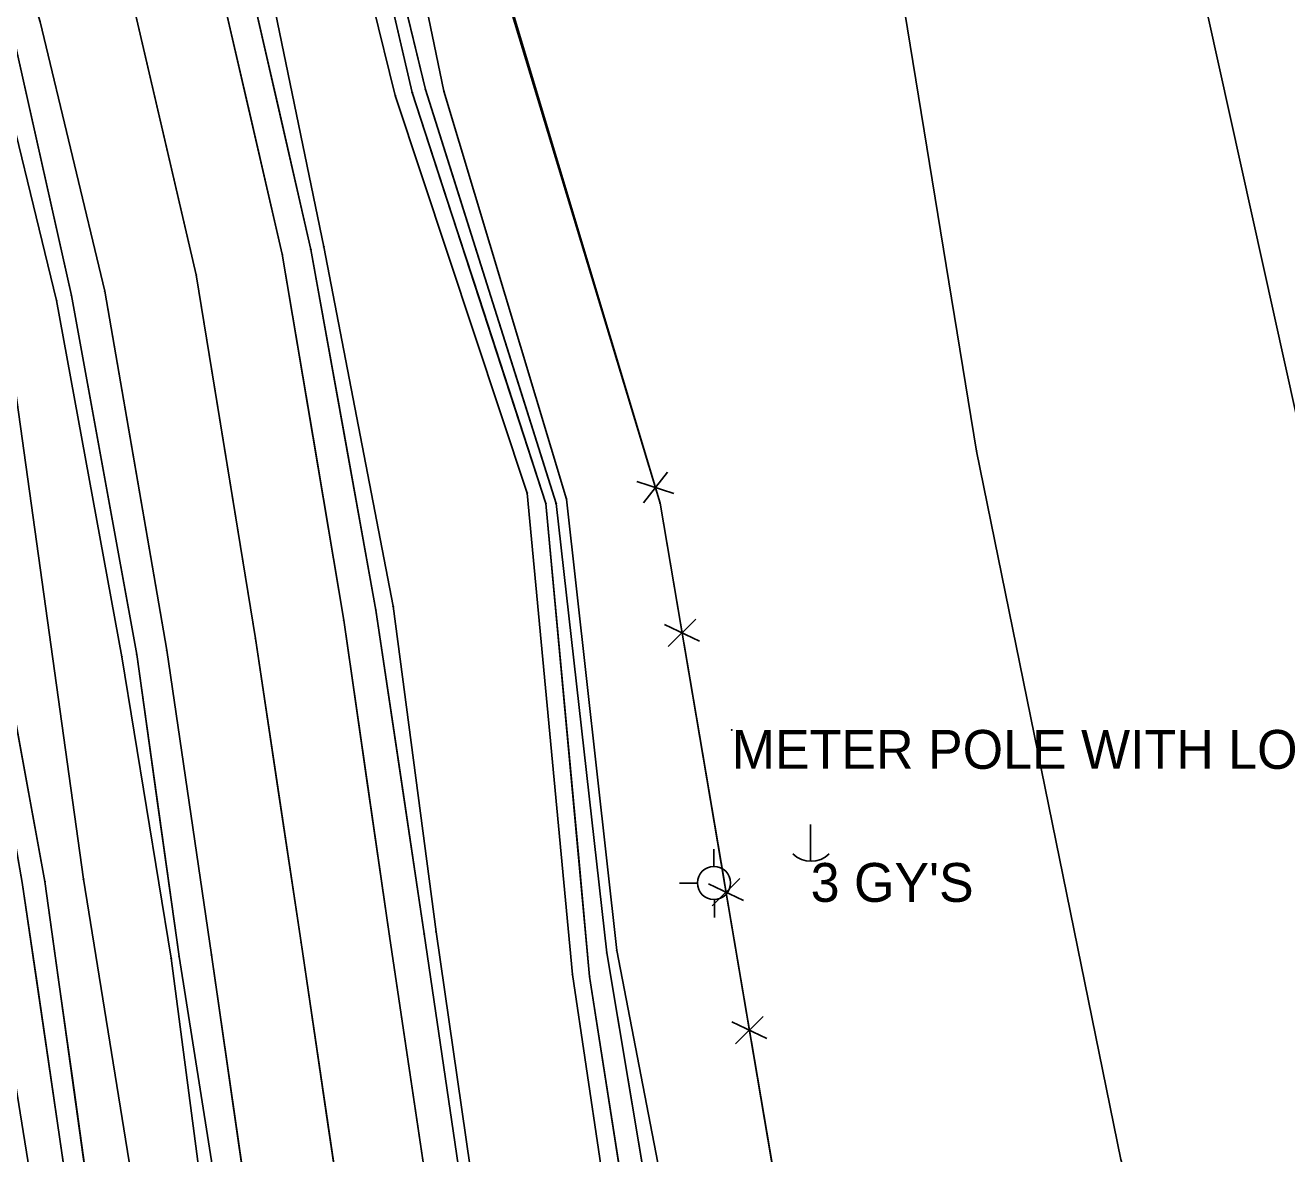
# Model space of a CAD drawing. Extents: x -99999 to 591807, y -99999 to 347168.
# Drawn here: x 588596 to 588758.3, y 345658.1 to 345803.3 of the extents above; entities that cross this region are included whole.
import ezdxf

# ---------------------------------------------------------------- set-up
doc = ezdxf.new("R2010")
doc.units = 0
for name, color, linetype in [('S_BREAKLINE', 7, 'Continuous'), ('S_DITCHLINE', 7, 'Continuous'), ('S_EDGE_PAVEMENT', 7, 'Continuous'), ('S_FENCE', 7, 'Continuous'), ('S_GRD_PT_SYM', 7, 'Continuous'), ('S_MISC_STRUCTURES_ANNOT', 7, 'Continuous'), ('S_MSC_PT_SYM', 7, 'Continuous'), ('S_PAVEMENT_CROWN', 7, 'Continuous'), ('S_RDW_PT_SYM', 7, 'Continuous'), ('S_SHOULDER', 7, 'Continuous'), ('S_UTILITY_POLE', 7, 'Continuous'), ('S_UTILITY_POLE_ANNOT', 7, 'Continuous')]:
    doc.layers.add(name, color=color, linetype=linetype)

msp = doc.modelspace()

# ---------------------------------------------------------------- linework, layer by layer
at = {"layer": 'S_BREAKLINE'}
for points in [[(588528.51, 345946.61), (588543.27, 345921.4), (588554.67, 345900.36), (588570.47, 345864.64), (588581.65, 345836.71), (588591.74, 345801.57), (588600, 345767.86), (588608.39, 345722.01), (588614.74, 345683.21), (588620.99, 345635.46), (588626.69, 345599.06), (588633.41, 345553.71), (588638.96, 345515.87), (588645.67, 345465.33), (588651.24, 345429.08)], [(588709.23, 345917.41), (588738.28, 345849.11), (588759.52, 345753.19), (588776.45, 345663.8), (588799.17, 345587.06), (588826.92, 345501.14), (588855.64, 345416.24), (588845.53, 345290.12), (588847.65, 345252.05)], [(588624.24, 345901.93), (588618.85, 345902.22), (588605.5, 345880.61), (588615.62, 345846.94), (588626.77, 345811.58), (588634.39, 345774.77), (588643.3, 345728.51), (588648.82, 345686.6), (588655.41, 345641.18), (588661.15, 345603.84), (588667.75, 345558.22), (588673.72, 345520.6), (588680.03, 345471.84), (588686.17, 345431.09), (588691.15, 345391.28), (588697.45, 345351.38), (588702.87, 345317.84), (588708.54, 345276.89), (588714.45, 345238.55), (588718.86, 345198.93), (588725.64, 345160.39), (588730.67, 345119.29), (588731.09, 345112.27)], [(588685.76, 345901.75), (588702.37, 345846.43), (588718.38, 345748.49), (588736.94, 345657.3), (588761.62, 345575.96), (588787.42, 345488.29), (588814.88, 345403.52), (588808.38, 345294.83), (588809.34, 345255.32)], [(588617.74, 345892.11), (588627.02, 345863.98), (588634.95, 345829.29), (588643.57, 345794.26), (588660.55, 345743.08), (588666.37, 345681.13), (588673.4, 345633.78), (588679.09, 345577.18), (588687.3, 345524.37), (588688.58, 345508.07), (588680.83, 345498.32), (588692.71, 345440.77), (588705.25, 345367.38), (588707.6, 345356.79), (588720.56, 345325.81), (588725.68, 345277.15), (588736.07, 345250.56), (588745.48, 345190.65)], [(588556.23, 345880.67), (588574, 345833.41), (588593.73, 345763.34), (588603.45, 345693.39), (588619.71, 345592.75), (588627.21, 345531.33), (588638.99, 345464.16), (588643.36, 345430.01), (588641.96, 345421.52), (588638.99, 345417.78), (588634.22, 345419.59)], [(588547.46, 345874.97), (588564.3, 345826.98), (588578.61, 345759.21), (588590.62, 345692.16), (588606.76, 345592.07), (588614.45, 345530.74), (588625.6, 345462.68), (588630.68, 345424.68)], [(588650.18, 345832.62), (588677.65, 345741.77), (588694.99, 345639.52), (588705.06, 345562.37), (588720.23, 345470.33), (588726.73, 345390.37), (588741.99, 345300.16), (588757.48, 345256.39)], [(588642.9, 345828.16), (588649.84, 345794.79), (588665.62, 345742.31), (588672.08, 345684.23), (588681.44, 345635.79), (588689.72, 345575.35), (588697.32, 345523.2), (588698.7, 345506.43), (588689.37, 345495.16), (588698.11, 345441.67), (588711.09, 345368.1), (588714.76, 345356.74), (588727.1, 345329.38), (588732.56, 345278.32), (588749.18, 345251.82), (588754.96, 345191.81)]]:
    msp.add_lwpolyline(points, dxfattribs=at)
at = {"layer": 'S_DITCHLINE'}
for points in [[(587981.38, 346490.49), (588040.72, 346433.29), (588105.81, 346371.99), (588170.92, 346308.42), (588239.53, 346243.97), (588298.87, 346183.24), (588365.05, 346118.27), (588381.6, 346095.52), (588429.37, 346040.98), (588482.84, 345982.86), (588529.72, 345920.18), (588553, 345879.12), (588569.51, 345828.65), (588585.87, 345761.88), (588598.5, 345693.11), (588612.58, 345591.71), (588620.74, 345530.5), (588634.95, 345464.48), (588639.41, 345427.12), (588638.6, 345425.11)], [(588518, 345935.85), (588529.72, 345920.18), (588541.36, 345899.65), (588553, 345879.12), (588557.13, 345866.5), (588561.25, 345853.89), (588565.38, 345841.27), (588569.51, 345828.65), (588573.6, 345811.96), (588577.69, 345795.26), (588581.78, 345778.57), (588585.87, 345761.88), (588589.03, 345744.69), (588592.18, 345727.49), (588595.34, 345710.3), (588598.5, 345693.11), (588600.26, 345680.44), (588602.02, 345667.76), (588603.78, 345655.08)], [(588621.84, 345893.69), (588629.96, 345863.53), (588637.77, 345829.01), (588645.75, 345794.64), (588662.97, 345741.75), (588668.58, 345680.85), (588676.01, 345633.28), (588682.43, 345576.4), (588689.45, 345524), (588691.57, 345507.82), (588684.16, 345496.45), (588694.48, 345441.14), (588707.93, 345367.35), (588709.31, 345356.72), (588722.33, 345326.05), (588729.11, 345277.3), (588737.99, 345251.31), (588749.45, 345190.72)], [(588621.84, 345893.69), (588625.9, 345878.61), (588629.96, 345863.53), (588633.86, 345846.27), (588637.77, 345829.01), (588641.76, 345811.83), (588645.75, 345794.64), (588650.05, 345781.42), (588654.36, 345768.2), (588658.66, 345754.97), (588662.97, 345741.75), (588664.37, 345726.53), (588665.78, 345711.3), (588667.18, 345696.08), (588668.58, 345680.85), (588672.3, 345657.07)], [(588623.83, 345894.43), (588633.9, 345864.11), (588639.2, 345829.29), (588647.45, 345795.03), (588664.28, 345741.74), (588670.78, 345683.92), (588678.95, 345635.24), (588686.91, 345576.28), (588693.9, 345523.47), (588694.27, 345507.04), (588686.96, 345495.31), (588696.5, 345441.16), (588709.78, 345368.13), (588712.25, 345356.79), (588724.62, 345327.12), (588730.93, 345277.7), (588741.81, 345251.89), (588752.43, 345192.99)], [(588623.83, 345894.43), (588628.87, 345879.27), (588633.9, 345864.11), (588636.55, 345846.7), (588639.2, 345829.29), (588643.32, 345812.16), (588647.45, 345795.03), (588651.65, 345781.71), (588655.86, 345768.39), (588660.07, 345755.06), (588664.28, 345741.74), (588665.9, 345727.28), (588667.53, 345712.83), (588669.16, 345698.37), (588670.78, 345683.92), (588674.87, 345659.58), (588678.95, 345635.24)], [(588551.64, 345878.63), (588567.65, 345827.94), (588583.59, 345761.1), (588595.57, 345692.94), (588610.45, 345591.57), (588618.47, 345530.47), (588631.48, 345463.26), (588636.49, 345429.05), (588637.41, 345423.3)], [(588551.64, 345878.63), (588555.64, 345865.95), (588559.65, 345853.28), (588563.65, 345840.61), (588567.65, 345827.94), (588571.64, 345811.23), (588575.62, 345794.52), (588579.61, 345777.81), (588583.59, 345761.1), (588586.59, 345744.06), (588589.58, 345727.02), (588592.57, 345709.98), (588595.57, 345692.94), (588597.43, 345680.27), (588599.29, 345667.6), (588601.15, 345654.93)]]:
    msp.add_lwpolyline(points, dxfattribs=at)
at = {"layer": 'S_EDGE_PAVEMENT'}
for points in [[(588533.24, 345949.77), (588549.25, 345924.48), (588560.38, 345903.49), (588576.85, 345867.18), (588587.36, 345838.19), (588597.88, 345803.73), (588606.19, 345769.06), (588614.17, 345722.86), (588619.93, 345683.64), (588626.83, 345635.93), (588632.16, 345599.5), (588638.76, 345554.26), (588644.16, 345517.2), (588651.6, 345466.73), (588656.93, 345429.09), (588662.9, 345388.64), (588668.52, 345349.79), (588673.64, 345313.6), (588679.62, 345272.35), (588684.7, 345235.84), (588690.61, 345195.28), (588696.28, 345156.82), (588702.9, 345112.49), (588707.26, 345082.66)], [(588541.25, 345937.13), (588549.25, 345924.48), (588560.38, 345903.49), (588568.61, 345885.34), (588576.85, 345867.18), (588582.1, 345852.68), (588587.36, 345838.19), (588592.62, 345820.96), (588597.88, 345803.73), (588602.04, 345786.4), (588606.19, 345769.06), (588610.18, 345745.96), (588614.17, 345722.86), (588617.05, 345703.25), (588619.93, 345683.64), (588623.38, 345659.78), (588626.83, 345635.93)], [(588569.44, 345935.94), (588581.55, 345913.63), (588598.25, 345876.18), (588610.02, 345844.44), (588620.66, 345810.06), (588629.03, 345773.8), (588636.94, 345726.71), (588642.85, 345686.06), (588649.62, 345640.56), (588655.14, 345603.07), (588661.71, 345557.63), (588667.45, 345519.25), (588674.48, 345470.93), (588680.21, 345431.06), (588685.9, 345390.75), (588691.57, 345351.74), (588696.47, 345317.62), (588702.47, 345275.72), (588708.04, 345237.72), (588713.42, 345199.12), (588719.22, 345159.84), (588725.04, 345117.97), (588728.1, 345099.84)], [(588575.49, 345924.78), (588581.55, 345913.63), (588589.9, 345894.9), (588598.25, 345876.18), (588604.14, 345860.31), (588610.02, 345844.44), (588615.34, 345827.25), (588620.66, 345810.06), (588624.84, 345791.93), (588629.03, 345773.8), (588632.99, 345750.25), (588636.94, 345726.71), (588639.89, 345706.39), (588642.85, 345686.06), (588646.23, 345663.31), (588649.62, 345640.56)]]:
    msp.add_lwpolyline(points, dxfattribs=at)
at = {"layer": 'S_FENCE'}
for p, q in [((588649.19, 345836.65), (588677.65, 345741.77)), ((588678.6, 345745.75), (588675.5, 345741.82)), ((588674.67, 345744.57), (588679.42, 345743)), ((588677.65, 345741.77), (588694.99, 345639.52)), ((588678.22, 345726.16), (588682.74, 345724.02)), ((588682.26, 345726.85), (588678.7, 345723.33)), ((588687.92, 345693.49), (588684.36, 345689.98)), ((588683.88, 345692.8), (588688.4, 345690.66)), ((588690.93, 345675.72), (588687.37, 345672.21)), ((588686.89, 345675.04), (588691.41, 345672.9))]:
    msp.add_line(p, q, dxfattribs=at)
for points in [[(588659.32, 345802.88), (588676.2, 345746.6)], [(588677.65, 345741.77), (588680.22, 345726.61)], [(588680.74, 345723.57), (588685.88, 345693.25)], [(588686.32, 345690.65), (588688.89, 345675.48)], [(588689.41, 345672.45), (588694.55, 345642.13)]]:
    msp.add_lwpolyline(points, dxfattribs=at)
at = {"layer": 'S_GRD_PT_SYM'}
for points in [[(588643.57, 345794.26), (588643.62, 345794.28), (588643.57, 345794.26), (588643.56, 345794.31), (588643.57, 345794.26), (588643.53, 345794.24), (588643.57, 345794.26), (588643.59, 345794.21)], [(588645.75, 345794.64), (588645.8, 345794.66), (588645.75, 345794.64), (588645.73, 345794.69), (588645.75, 345794.64), (588645.7, 345794.63), (588645.75, 345794.64), (588645.76, 345794.6)], [(588647.45, 345795.03), (588647.5, 345795.05), (588647.45, 345795.03), (588647.43, 345795.08), (588647.45, 345795.03), (588647.4, 345795.02), (588647.45, 345795.03), (588647.46, 345794.99)], [(588649.84, 345794.79), (588649.88, 345794.8), (588649.84, 345794.79), (588649.82, 345794.84), (588649.84, 345794.79), (588649.79, 345794.77), (588649.84, 345794.79), (588649.85, 345794.74)], [(588634.39, 345774.77), (588634.44, 345774.78), (588634.39, 345774.77), (588634.38, 345774.82), (588634.39, 345774.77), (588634.34, 345774.76), (588634.39, 345774.77), (588634.4, 345774.72)], [(588600, 345767.86), (588600.05, 345767.87), (588600, 345767.86), (588599.99, 345767.91), (588600, 345767.86), (588599.95, 345767.85), (588600, 345767.86), (588600.01, 345767.81)], [(588718.38, 345748.49), (588718.43, 345748.5), (588718.38, 345748.49), (588718.37, 345748.54), (588718.38, 345748.49), (588718.33, 345748.48), (588718.38, 345748.49), (588718.39, 345748.44)], [(588660.55, 345743.08), (588660.6, 345743.08), (588660.55, 345743.08), (588660.55, 345743.13), (588660.55, 345743.08), (588660.5, 345743.07), (588660.55, 345743.08), (588660.56, 345743.03)], [(588665.62, 345742.31), (588665.67, 345742.32), (588665.62, 345742.31), (588665.62, 345742.36), (588665.62, 345742.31), (588665.57, 345742.31), (588665.62, 345742.31), (588665.63, 345742.26)], [(588662.97, 345741.75), (588663.02, 345741.75), (588662.97, 345741.75), (588662.96, 345741.8), (588662.97, 345741.75), (588662.92, 345741.74), (588662.97, 345741.75), (588662.97, 345741.7)], [(588664.28, 345741.74), (588664.33, 345741.75), (588664.28, 345741.74), (588664.27, 345741.79), (588664.28, 345741.74), (588664.23, 345741.73), (588664.28, 345741.74), (588664.28, 345741.69)], [(588677.65, 345741.77), (588677.7, 345741.78), (588677.65, 345741.77), (588677.64, 345741.82), (588677.65, 345741.77), (588677.6, 345741.76), (588677.65, 345741.77), (588677.66, 345741.72)], [(588643.3, 345728.51), (588643.35, 345728.52), (588643.3, 345728.51), (588643.29, 345728.56), (588643.3, 345728.51), (588643.25, 345728.5), (588643.3, 345728.51), (588643.31, 345728.46)], [(588608.39, 345722.01), (588608.44, 345722.02), (588608.39, 345722.01), (588608.39, 345722.06), (588608.39, 345722.01), (588608.35, 345722), (588608.39, 345722.01), (588608.4, 345721.96)], [(588598.5, 345693.11), (588598.55, 345693.12), (588598.5, 345693.11), (588598.49, 345693.16), (588598.5, 345693.11), (588598.45, 345693.1), (588598.5, 345693.11), (588598.51, 345693.06)], [(588603.45, 345693.39), (588603.5, 345693.4), (588603.45, 345693.39), (588603.44, 345693.44), (588603.45, 345693.39), (588603.4, 345693.39), (588603.45, 345693.39), (588603.46, 345693.35)], [(588648.82, 345686.6), (588648.87, 345686.6), (588648.82, 345686.6), (588648.82, 345686.65), (588648.82, 345686.6), (588648.77, 345686.59), (588648.82, 345686.6), (588648.83, 345686.55)], [(588670.78, 345683.92), (588670.83, 345683.93), (588670.78, 345683.92), (588670.77, 345683.97), (588670.78, 345683.92), (588670.73, 345683.91), (588670.78, 345683.92), (588670.79, 345683.87)], [(588672.08, 345684.23), (588672.13, 345684.24), (588672.08, 345684.23), (588672.07, 345684.28), (588672.08, 345684.23), (588672.04, 345684.22), (588672.08, 345684.23), (588672.09, 345684.18)], [(588614.74, 345683.21), (588614.79, 345683.21), (588614.74, 345683.21), (588614.73, 345683.26), (588614.74, 345683.21), (588614.69, 345683.2), (588614.74, 345683.21), (588614.74, 345683.16)], [(588666.37, 345681.13), (588666.42, 345681.13), (588666.37, 345681.13), (588666.36, 345681.18), (588666.37, 345681.13), (588666.32, 345681.12), (588666.37, 345681.13), (588666.38, 345681.08)], [(588668.58, 345680.85), (588668.63, 345680.86), (588668.58, 345680.85), (588668.58, 345680.9), (588668.58, 345680.85), (588668.53, 345680.85), (588668.58, 345680.85), (588668.59, 345680.81)]]:
    msp.add_lwpolyline(points, close=True, dxfattribs=at)
at = {"layer": 'S_MSC_PT_SYM'}
for points in [[(588677.65, 345741.77), (588677.65, 345741.82), (588677.65, 345741.77), (588677.6, 345741.77), (588677.65, 345741.77), (588677.65, 345741.72), (588677.65, 345741.77), (588677.7, 345741.77)], [(588686.87, 345712.59), (588686.87, 345712.64), (588686.87, 345712.59), (588686.82, 345712.59), (588686.87, 345712.59), (588686.87, 345712.54), (588686.87, 345712.59), (588686.92, 345712.59)]]:
    msp.add_lwpolyline(points, dxfattribs=at)
at = {"layer": 'S_PAVEMENT_CROWN'}
for points in [[(588560.06, 345929.96), (588571.31, 345908.67), (588587.66, 345872.48), (588598.75, 345842.4), (588609.73, 345806.6), (588617.97, 345771.15), (588625.58, 345724.38), (588631.45, 345685.22), (588638.38, 345638.52), (588643.85, 345601.75), (588650.48, 345555.87), (588655.89, 345518.36), (588662.96, 345470.1), (588668.73, 345430.24), (588674.46, 345389.14), (588680.31, 345350.53), (588685.24, 345315.85), (588691.31, 345273.41), (588696.56, 345236.41), (588702.29, 345197.14), (588707.93, 345158.2), (588714.7, 345114.95), (588717.67, 345091.03)], [(588560.06, 345929.96), (588571.31, 345908.67), (588579.49, 345890.58), (588587.66, 345872.48), (588593.21, 345857.44), (588598.75, 345842.4), (588604.24, 345824.5), (588609.73, 345806.6), (588613.85, 345788.88), (588617.97, 345771.15), (588621.77, 345747.77), (588625.58, 345724.38), (588628.52, 345704.8), (588631.45, 345685.22), (588634.91, 345661.87), (588638.38, 345638.52)]]:
    msp.add_lwpolyline(points, dxfattribs=at)
at = {"layer": 'S_RDW_PT_SYM'}
for points in [[(588629.03, 345773.8), (588629.08, 345773.8), (588629.03, 345773.8), (588629.02, 345773.84), (588629.03, 345773.8), (588628.98, 345773.79), (588629.03, 345773.8), (588629.04, 345773.75)], [(588632.71, 345774.41), (588632.76, 345774.42), (588632.71, 345774.41), (588632.7, 345774.46), (588632.71, 345774.41), (588632.66, 345774.4), (588632.71, 345774.41), (588632.72, 345774.36)], [(588617.97, 345771.15), (588618.01, 345771.16), (588617.97, 345771.15), (588617.96, 345771.2), (588617.97, 345771.15), (588617.92, 345771.14), (588617.97, 345771.15), (588617.97, 345771.1)], [(588601.9, 345768.49), (588601.95, 345768.5), (588601.9, 345768.49), (588601.89, 345768.54), (588601.9, 345768.49), (588601.85, 345768.48), (588601.9, 345768.49), (588601.91, 345768.44)], [(588606.19, 345769.06), (588606.24, 345769.07), (588606.19, 345769.06), (588606.18, 345769.11), (588606.19, 345769.06), (588606.14, 345769.05), (588606.19, 345769.06), (588606.2, 345769.01)], [(588641.09, 345728.01), (588641.14, 345728.02), (588641.09, 345728.01), (588641.09, 345728.06), (588641.09, 345728.01), (588641.04, 345728), (588641.09, 345728.01), (588641.1, 345727.96)], [(588636.94, 345726.71), (588636.99, 345726.72), (588636.94, 345726.71), (588636.93, 345726.76), (588636.94, 345726.71), (588636.89, 345726.7), (588636.94, 345726.71), (588636.95, 345726.66)], [(588625.58, 345724.38), (588625.63, 345724.39), (588625.58, 345724.38), (588625.58, 345724.43), (588625.58, 345724.38), (588625.53, 345724.37), (588625.58, 345724.38), (588625.59, 345724.33)], [(588614.17, 345722.86), (588614.22, 345722.86), (588614.17, 345722.86), (588614.17, 345722.91), (588614.17, 345722.86), (588614.12, 345722.85), (588614.17, 345722.86), (588614.18, 345722.81)], [(588610.3, 345722.31), (588610.35, 345722.31), (588610.3, 345722.31), (588610.29, 345722.36), (588610.3, 345722.31), (588610.25, 345722.3), (588610.3, 345722.31), (588610.31, 345722.26)], [(588642.85, 345686.06), (588642.9, 345686.07), (588642.85, 345686.06), (588642.84, 345686.11), (588642.85, 345686.06), (588642.8, 345686.06), (588642.85, 345686.06), (588642.85, 345686.01)], [(588647.29, 345686.34), (588647.34, 345686.35), (588647.29, 345686.34), (588647.29, 345686.39), (588647.29, 345686.34), (588647.24, 345686.33), (588647.29, 345686.34), (588647.3, 345686.29)], [(588631.45, 345685.22), (588631.5, 345685.23), (588631.45, 345685.22), (588631.44, 345685.27), (588631.45, 345685.22), (588631.4, 345685.22), (588631.45, 345685.22), (588631.46, 345685.17)], [(588615.76, 345683.42), (588615.8, 345683.43), (588615.76, 345683.42), (588615.75, 345683.47), (588615.76, 345683.42), (588615.71, 345683.41), (588615.76, 345683.42), (588615.76, 345683.37)], [(588619.93, 345683.64), (588619.98, 345683.64), (588619.93, 345683.64), (588619.93, 345683.69), (588619.93, 345683.64), (588619.88, 345683.63), (588619.93, 345683.64), (588619.94, 345683.59)]]:
    msp.add_lwpolyline(points, close=True, dxfattribs=at)
at = {"layer": 'S_SHOULDER'}
for points in [[(588530.37, 345947.67), (588545.69, 345922.75), (588556.57, 345901.4), (588573.04, 345865.81), (588583.59, 345837.05), (588594.28, 345802.6), (588601.9, 345768.49), (588610.3, 345722.31), (588615.76, 345683.42), (588623.32, 345635.72), (588628.53, 345599.32), (588635.42, 345554.02), (588640.61, 345516.64), (588647.48, 345465.58), (588653.55, 345426.29)], [(588573.14, 345938.09), (588585.12, 345914.74), (588602.08, 345877.76), (588613.81, 345846.29), (588624.36, 345810.99), (588632.71, 345774.41), (588641.09, 345728.01), (588647.29, 345686.34), (588653.97, 345640.89), (588659.33, 345603.64), (588665.84, 345557.97), (588671.97, 345520.33), (588678.33, 345471.45), (588684.51, 345430.85), (588689.91, 345391.05)], [(588538.03, 345935.21), (588545.69, 345922.75), (588556.57, 345901.4), (588564.81, 345883.61), (588573.04, 345865.81), (588578.32, 345851.43), (588583.59, 345837.05), (588588.94, 345819.82), (588594.28, 345802.6), (588598.09, 345785.54), (588601.9, 345768.49), (588606.1, 345745.4), (588610.3, 345722.31), (588613.03, 345702.86), (588615.76, 345683.42), (588619.54, 345659.57), (588623.32, 345635.72)], [(588579.13, 345926.41), (588585.12, 345914.74), (588593.6, 345896.25), (588602.08, 345877.76), (588607.95, 345862.03), (588613.81, 345846.29), (588619.08, 345828.64), (588624.36, 345810.99), (588628.53, 345792.7), (588632.71, 345774.41), (588636.9, 345751.21), (588641.09, 345728.01), (588644.19, 345707.17), (588647.29, 345686.34), (588650.63, 345663.61), (588653.97, 345640.89)]]:
    msp.add_lwpolyline(points, dxfattribs=at)
at = {"layer": 'S_UTILITY_POLE'}
for p, q in [((588697.02, 345700.41), (588697.02, 345695.69)), ((588684.59, 345695.01), (588684.59, 345697.26)), ((588682.49, 345692.88), (588680.17, 345692.88)), ((588684.66, 345688.46), (588684.66, 345690.79))]:
    msp.add_line(p, q, dxfattribs=at)
msp.add_circle((588684.59, 345692.9), 2.13, dxfattribs=at)
msp.add_arc((588697.08, 345699.11), 3.41, 226.3972, 313.6028, dxfattribs=at)

# ---------------------------------------------------------------- texts
at = {"layer": 'S_MISC_STRUCTURES_ANNOT'}
msp.add_text('METER POLE WITH LOOP', height=5, dxfattribs=at).set_placement((588686.87, 345707.59))
at = {"layer": 'S_UTILITY_POLE_ANNOT'}
msp.add_text("3 GY'S", height=5, dxfattribs=at).set_placement((588697.03, 345690.47))

doc.saveas('drawing.dxf')
